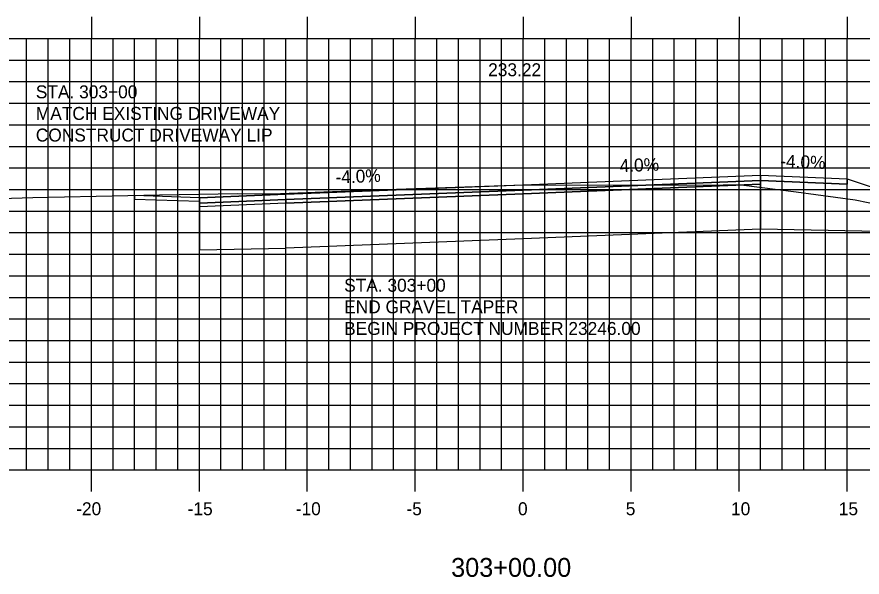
# Model space of a CAD drawing. Extents: x 1136767 to 1136937, y 608981 to 609091.
# Drawn here: x 1136826.93 to 1136866.08, y 609010.37 to 609036.34 of the extents above; entities that cross this region are included whole.
import ezdxf

# ---------------------------------------------------------------- set-up
doc = ezdxf.new("R2010")
doc.units = 0
for name, color, linetype in [('ANNOTATION', 7, 'Continuous'), ('D_Roadway_Centerline', 7, 'Continuous'), ('D_Roadway_Centerline_Text', 7, 'Continuous'), ('D_Roadway_Edge_Shoulder', 7, 'Continuous'), ('D_Roadway_Edge_TW', 7, 'Continuous'), ('D_Roadway_Pavement', 7, 'Continuous'), ('D_Roadway_SubGrade', 7, 'Continuous'), ('H_V ANNOTATION', 7, 'Continuous'), ('MAJOR', 7, 'Continuous'), ('MINOR', 7, 'Continuous'), ('S_Roadway_Centerline', 7, 'Continuous')]:
    doc.layers.add(name, color=color, linetype=linetype)

msp = doc.modelspace()

# ---------------------------------------------------------------- linework, layer by layer
msp.add_lwpolyline([(1136835.382, 609027.955), (1136835.383, 609027.955), (1136839.383, 609028.115), (1136850.383, 609028.555), (1136861.383, 609028.995), (1136865.383, 609028.835), (1136873.107, 609026.26), (1136876.107, 609025.26), (1136879.874, 609027.144), (1136881.124, 609027.694), (1136882.374, 609028.091), (1136883.624, 609028.338), (1136884.874, 609028.433)])
at = {"layer": 'D_Roadway_Edge_Shoulder'}
for points in [[(1136861.383, 609028.995), (1136865.383, 609028.835), (1136865.383, 609028.585), (1136861.383, 609028.745)], [(1136839.383, 609028.115), (1136835.383, 609027.955), (1136835.383, 609027.705), (1136839.383, 609027.865)], [(1136835.383, 609027.955), (1136832.383, 609028.058), (1136832.383, 609027.891), (1136835.383, 609027.788)]]:
    msp.add_lwpolyline(points, close=True, dxfattribs=at)
at = {"layer": 'D_Roadway_Edge_TW'}
for points in [[(1136839.383, 609027.865), (1136839.383, 609028.115), (1136850.383, 609028.555), (1136861.383, 609028.995), (1136861.383, 609028.745), (1136850.383, 609028.305)], [(1136839.383, 609027.698), (1136835.383, 609027.538), (1136835.383, 609027.705), (1136839.383, 609027.865)]]:
    msp.add_lwpolyline(points, close=True, dxfattribs=at)
at = {"layer": 'D_Roadway_Pavement'}
msp.add_lwpolyline([(1136839.383, 609027.698), (1136839.383, 609027.865), (1136850.383, 609028.305), (1136861.383, 609028.745), (1136861.383, 609028.578), (1136850.383, 609028.138)], close=True, dxfattribs=at)
at = {"layer": 'D_Roadway_SubGrade'}
for points in [[(1136839.383, 609025.615), (1136839.383, 609027.698), (1136850.383, 609028.138), (1136861.383, 609028.578), (1136861.383, 609026.495), (1136850.383, 609026.055)], [(1136861.383, 609028.578), (1136861.383, 609028.745), (1136865.383, 609028.585), (1136865.383, 609028.835), (1136865.383, 609028.835), (1136873.107, 609026.26), (1136861.383, 609026.495)], [(1136835.382, 609026.955), (1136835.383, 609025.535), (1136839.383, 609025.615), (1136839.383, 609027.698), (1136839.383, 609027.865), (1136835.383, 609027.705), (1136835.383, 609027.955), (1136835.382, 609027.955)]]:
    msp.add_lwpolyline(points, close=True, dxfattribs=at)
at = {"layer": 'MAJOR'}
for p, q in [((1136830.383, 609036.337), (1136830.383, 609035.335)), ((1136835.383, 609036.337), (1136835.383, 609035.335)), ((1136840.383, 609036.337), (1136840.383, 609035.335)), ((1136845.383, 609036.337), (1136845.383, 609035.335)), ((1136850.383, 609036.337), (1136850.383, 609035.335)), ((1136855.383, 609036.337), (1136855.383, 609035.335)), ((1136860.383, 609036.337), (1136860.383, 609035.335)), ((1136865.383, 609036.337), (1136865.383, 609035.335)), ((1136780.383, 609035.335), (1136920.383, 609035.335)), ((1136780.383, 609035.335), (1136920.383, 609035.335)), ((1136830.383, 609015.335), (1136830.383, 609035.335)), ((1136835.383, 609015.335), (1136835.383, 609035.335)), ((1136840.383, 609015.335), (1136840.383, 609035.335)), ((1136845.383, 609015.335), (1136845.383, 609035.335)), ((1136850.383, 609015.335), (1136850.383, 609035.335)), ((1136855.383, 609015.335), (1136855.383, 609035.335)), ((1136860.383, 609015.335), (1136860.383, 609035.335)), ((1136865.383, 609015.335), (1136865.383, 609035.335)), ((1136780.383, 609030.335), (1136920.383, 609030.335)), ((1136780.383, 609025.335), (1136920.383, 609025.335)), ((1136780.383, 609020.335), (1136920.383, 609020.335)), ((1136780.383, 609015.335), (1136920.383, 609015.335)), ((1136780.383, 609015.335), (1136920.383, 609015.335)), ((1136830.383, 609014.333), (1136830.383, 609015.335)), ((1136835.383, 609014.333), (1136835.383, 609015.335)), ((1136840.383, 609014.333), (1136840.383, 609015.335)), ((1136845.383, 609014.333), (1136845.383, 609015.335)), ((1136850.383, 609014.333), (1136850.383, 609015.335)), ((1136855.383, 609014.333), (1136855.383, 609015.335)), ((1136860.383, 609014.333), (1136860.383, 609015.335)), ((1136865.383, 609014.333), (1136865.383, 609015.335))]:
    msp.add_line(p, q, dxfattribs=at)
at = {"layer": 'MINOR'}
for p, q in [((1136827.383, 609015.335), (1136827.383, 609035.335)), ((1136828.383, 609015.335), (1136828.383, 609035.335)), ((1136829.383, 609015.335), (1136829.383, 609035.335)), ((1136831.383, 609015.335), (1136831.383, 609035.335)), ((1136832.383, 609015.335), (1136832.383, 609035.335)), ((1136833.383, 609015.335), (1136833.383, 609035.335)), ((1136834.383, 609015.335), (1136834.383, 609035.335)), ((1136836.383, 609015.335), (1136836.383, 609035.335)), ((1136837.383, 609015.335), (1136837.383, 609035.335)), ((1136838.383, 609015.335), (1136838.383, 609035.335)), ((1136839.383, 609015.335), (1136839.383, 609035.335)), ((1136841.383, 609015.335), (1136841.383, 609035.335)), ((1136842.383, 609015.335), (1136842.383, 609035.335)), ((1136843.383, 609015.335), (1136843.383, 609035.335)), ((1136844.383, 609015.335), (1136844.383, 609035.335)), ((1136846.383, 609015.335), (1136846.383, 609035.335)), ((1136847.383, 609015.335), (1136847.383, 609035.335)), ((1136848.383, 609015.335), (1136848.383, 609035.335)), ((1136849.383, 609015.335), (1136849.383, 609035.335)), ((1136851.383, 609015.335), (1136851.383, 609035.335)), ((1136852.383, 609015.335), (1136852.383, 609035.335)), ((1136853.383, 609015.335), (1136853.383, 609035.335)), ((1136854.383, 609015.335), (1136854.383, 609035.335)), ((1136856.383, 609015.335), (1136856.383, 609035.335)), ((1136857.383, 609015.335), (1136857.383, 609035.335)), ((1136858.383, 609015.335), (1136858.383, 609035.335)), ((1136859.383, 609015.335), (1136859.383, 609035.335)), ((1136861.383, 609015.335), (1136861.383, 609035.335)), ((1136862.383, 609015.335), (1136862.383, 609035.335)), ((1136863.383, 609015.335), (1136863.383, 609035.335)), ((1136864.383, 609015.335), (1136864.383, 609035.335)), ((1136780.383, 609034.335), (1136920.383, 609034.335)), ((1136780.383, 609033.335), (1136920.383, 609033.335)), ((1136780.383, 609032.335), (1136920.383, 609032.335)), ((1136780.383, 609031.335), (1136920.383, 609031.335)), ((1136780.383, 609029.335), (1136920.383, 609029.335)), ((1136780.383, 609028.335), (1136920.383, 609028.335)), ((1136780.383, 609027.335), (1136920.383, 609027.335)), ((1136780.383, 609026.335), (1136920.383, 609026.335)), ((1136780.383, 609024.335), (1136920.383, 609024.335)), ((1136780.383, 609023.335), (1136920.383, 609023.335)), ((1136780.383, 609022.335), (1136920.383, 609022.335)), ((1136780.383, 609021.335), (1136920.383, 609021.335)), ((1136780.383, 609019.335), (1136920.383, 609019.335)), ((1136780.383, 609018.335), (1136920.383, 609018.335)), ((1136780.383, 609017.335), (1136920.383, 609017.335)), ((1136780.383, 609016.335), (1136920.383, 609016.335))]:
    msp.add_line(p, q, dxfattribs=at)
at = {"layer": 'S_Roadway_Centerline'}
msp.add_lwpolyline([(1136822.194, 609027.792), (1136827.669, 609027.966), (1136833.537, 609028.081), (1136837.169, 609028.144), (1136838.739, 609028.139), (1136843.157, 609028.309), (1136849.946, 609028.538), (1136859.641, 609028.552), (1136860.485, 609028.559), (1136863.029, 609028.225), (1136865.76, 609027.861), (1136866.958, 609027.606), (1136869.62, 609027.988), (1136872.643, 609028.131), (1136874.07, 609028.265), (1136888.517, 609028.49), (1136889.712, 609028.507), (1136889.937, 609028.505), (1136905.048, 609028.329), (1136909.628, 609028.345), (1136920.383, 609028.314)], dxfattribs=at)

# ---------------------------------------------------------------- texts
at = {"layer": 'ANNOTATION'}
for s, p in [('STA. 303+00', (1136827.806, 609032.563)), ('MATCH EXISTING DRIVEWAY', (1136827.806, 609031.561)), ('CONSTRUCT DRIVEWAY LIP', (1136827.806, 609030.559)), ('STA. 303+00', (1136842.089, 609023.597)), ('END GRAVEL TAPER', (1136842.089, 609022.595)), ('BEGIN PROJECT NUMBER 23246.00', (1136842.089, 609021.593))]:
    msp.add_text(s, height=0.6, dxfattribs=at).set_placement(p)
for s, rotation, p in [('4.0%', 2.2906, (1136854.86, 609029.135)), ('-4.0%', 357.7094, (1136862.279, 609029.36)), ('-4.0%', 2.2906, (1136841.699, 609028.608))]:
    msp.add_text(s, height=0.6, rotation=rotation, dxfattribs=at).set_placement(p)
at = {"layer": 'D_Roadway_Centerline'}
for s, p in [('C', (1136850.378, 609028.555)), ('L', (1136850.383, 609028.548))]:
    msp.add_text(s, height=0.0146, dxfattribs=at).set_placement(p)
at = {"layer": 'D_Roadway_Centerline_Text'}
msp.add_text('233.22', height=0.6, dxfattribs=at).set_placement((1136848.759, 609033.587))
at = {"layer": 'H_V ANNOTATION'}
for s, height, p in [('-20', 0.6, (1136829.677, 609013.235)), ('-15', 0.6, (1136834.84, 609013.235)), ('-10', 0.6, (1136839.848, 609013.235)), ('-5', 0.6, (1136844.974, 609013.235)), ('0', 0.6, (1136850.142, 609013.235)), ('5', 0.6, (1136855.134, 609013.235)), ('10', 0.6, (1136860.009, 609013.235)), ('15', 0.6, (1136865.001, 609013.235)), ('303+00.00', 0.875, (1136847.044, 609010.378))]:
    msp.add_text(s, height=height, dxfattribs=at).set_placement(p)
at = {"layer": 'S_Roadway_Centerline'}
for s, p in [('L', (1136849.937, 609028.53)), ('C', (1136849.94, 609028.538))]:
    msp.add_text(s, height=0.0146, dxfattribs=at).set_placement(p)

doc.saveas('drawing.dxf')
